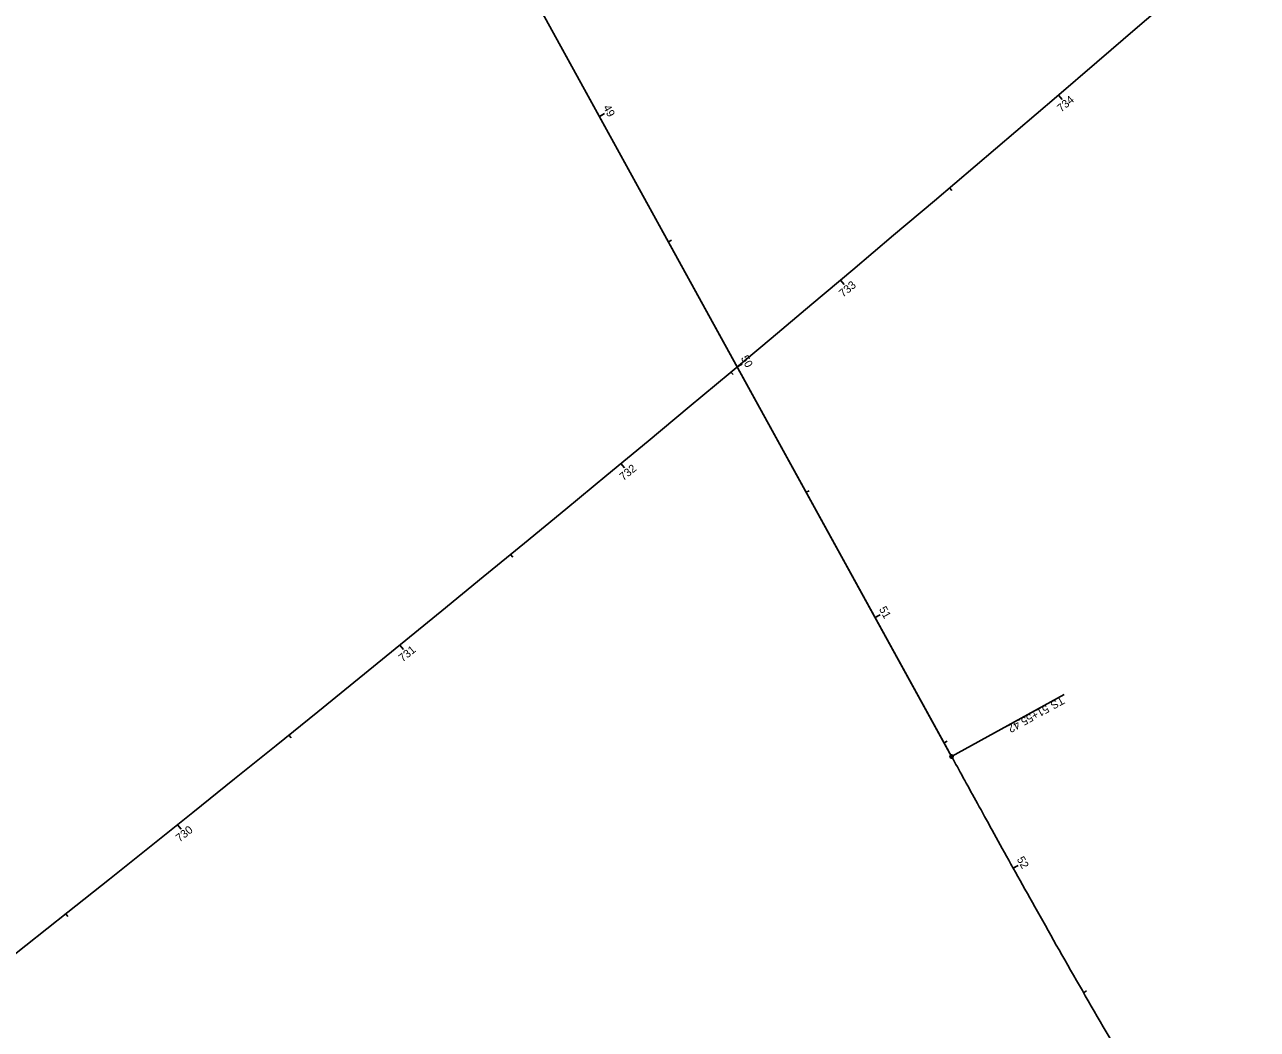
# Model space of a CAD drawing. Extents: x 1492452 to 1496782, y 514026 to 517659.
# Drawn here: x 1494046.8 to 1494477.9, y 515125.3 to 515476.4 of the extents above; entities that cross this region are included whole.
import ezdxf

# ---------------------------------------------------------------- set-up
doc = ezdxf.new("R2010")
doc.units = 0
for name, color, linetype in [('Default', 7, 'Continuous'), ('DT_X_Contour_Minor', 7, 'Continuous'), ('DT_X_TIN_Hull', 7, 'Continuous'), ('GE_X_Cells', 7, 'Continuous'), ('PV_X_EOP', 7, 'Continuous'), ('PV_X_Shoulder_Aggregate', 7, 'Continuous'), ('RD_X_GR_Rt', 7, 'Continuous'), ('RD_X_Wall', 7, 'Continuous'), ('SV_X_Top_of_Bank', 7, 'Continuous'), ('UT_X_Water_Cells', 7, 'Continuous'), ('VG_X_Cells', 7, 'Continuous'), ('XS_X_Ground_Line', 7, 'Continuous')]:
    doc.layers.add(name, color=color, linetype=linetype)

msp = doc.modelspace()

# ---------------------------------------------------------------- linework, layer by layer
at = {"layer": 'Default'}
msp.add_arc((1486425.91, 524780.42), 12277.67, 302.444021, 313.600151, dxfattribs=at)
at = {"layer": 'DT_X_Contour_Minor'}
msp.add_line((1494295.99, 515356.78), (1494297.74, 515357.74), dxfattribs=at)
at = {"layer": 'DT_X_TIN_Hull'}
for p, q in [((1494408.32, 515451.84), (1494409.62, 515450.32)), ((1494370.26, 515419.41), (1494371.04, 515418.5)), ((1494332.08, 515387.14), (1494333.36, 515385.61)), ((1494293.76, 515355.02), (1494294.53, 515354.1)), ((1494255.31, 515323.06), (1494256.58, 515321.52)), ((1494216.73, 515291.25), (1494217.49, 515290.32)), ((1494178.02, 515259.6), (1494179.28, 515258.05)), ((1494139.18, 515228.11), (1494139.94, 515227.18)), ((1494100.22, 515196.78), (1494101.47, 515195.22)), ((1494061.12, 515165.6), (1494061.87, 515164.66))]:
    msp.add_line(p, q, dxfattribs=at)
at = {"layer": 'GE_X_Cells'}
msp.add_arc((1486425.91, 524780.42), 12277.67, 302.444021, 313.600151, dxfattribs=at)
at = {"layer": 'PV_X_EOP'}
msp.add_line((1494370.94, 515220.63), (1494410.36, 515242.33), dxfattribs=at)
msp.add_circle((1494370.94, 515220.63), 0.6, dxfattribs=at)
at = {"layer": 'PV_X_Shoulder_Aggregate'}
for p, q in [((1494247.77, 515444.38), (1494249.52, 515445.35)), ((1494271.88, 515400.58), (1494272.93, 515401.16)), ((1494295.99, 515356.78), (1494297.74, 515357.74)), ((1494320.1, 515312.98), (1494321.15, 515313.55)), ((1494344.21, 515269.17), (1494345.97, 515270.14)), ((1494368.33, 515225.37), (1494369.38, 515225.95)), ((1494392.49, 515181.6), (1494394.24, 515182.57)), ((1494417.09, 515138.07), (1494418.13, 515138.67))]:
    msp.add_line(p, q, dxfattribs=at)
at = {"layer": 'RD_X_GR_Rt'}
msp.add_line((1494370.94, 515220.63), (1494410.36, 515242.33), dxfattribs=at)
msp.add_circle((1494370.94, 515220.63), 0.6, dxfattribs=at)
at = {"layer": 'RD_X_Wall'}
for p, q in [((1494247.77, 515444.38), (1494248.82, 515444.96)), ((1494295.99, 515356.78), (1494297.74, 515357.74)), ((1494344.21, 515269.17), (1494345.26, 515269.75)), ((1494392.49, 515181.6), (1494393.54, 515182.18))]:
    msp.add_line(p, q, dxfattribs=at)
at = {"layer": 'SV_X_Top_of_Bank'}
for q in [(1494370, 515222.33), (1494370.94, 515220.63)]:
    msp.add_line((1494054.87, 515794.8), q, dxfattribs=at)
msp.add_open_spline([(1494370.94, 515220.63), (1494373.62, 515215.76), (1494378.97, 515206.03), (1494389.71, 515186.57), (1494403.23, 515162.3), (1494419.72, 515133.34), (1494436.64, 515104.61), (1494451.2, 515080.96), (1494463.19, 515062.25), (1494469.31, 515052.97), (1494472.4, 515048.36)], degree=3, dxfattribs=at)
msp.add_open_spline([(1494370.94, 515220.63), (1494373.62, 515215.76), (1494378.97, 515206.03), (1494389.71, 515186.57), (1494403.23, 515162.3), (1494419.72, 515133.34), (1494436.64, 515104.61), (1494451.2, 515080.96), (1494463.19, 515062.25), (1494469.31, 515052.97), (1494472.4, 515048.36)], degree=3, dxfattribs=at)
at = {"layer": 'UT_X_Water_Cells'}
for p, q in [((1494408.32, 515451.84), (1494409.1, 515450.93)), ((1494332.08, 515387.14), (1494332.85, 515386.22)), ((1494255.31, 515323.06), (1494256.07, 515322.13)), ((1494178.02, 515259.6), (1494178.78, 515258.67)), ((1494100.22, 515196.78), (1494101.47, 515195.22))]:
    msp.add_line(p, q, dxfattribs=at)
at = {"layer": 'VG_X_Cells'}
msp.add_line((1494100.22, 515196.78), (1494101.47, 515195.22), dxfattribs=at)
at = {"layer": 'XS_X_Ground_Line'}
msp.add_line((1494370.94, 515220.63), (1494410.36, 515242.33), dxfattribs=at)
msp.add_circle((1494370.94, 515220.63), 0.6, dxfattribs=at)

# ---------------------------------------------------------------- texts
at = {"layer": 'DT_X_Contour_Minor'}
msp.add_text('50', height=2.8, rotation=298.8312, dxfattribs=at).set_placement((1494297.16, 515359.93))
at = {"layer": 'DT_X_TIN_Hull'}
for s, rotation, p in [('734', 40.5534, (1494409.3, 515445.71)), ('733', 40.0868, (1494332.99, 515380.98)), ('732', 39.6201, (1494256.16, 515316.89)), ('731', 39.1534, (1494178.95, 515253.53)), ('730', 38.6868, (1494100.97, 515190.59))]:
    msp.add_text(s, height=2.8, rotation=rotation, dxfattribs=at).set_placement(p)
at = {"layer": 'PV_X_EOP'}
for s, p in [('TS', (1494409.4, 515241.74)), ('51+55.42', (1494404.06, 515238.81))]:
    msp.add_text(s, height=2.8, rotation=208.8312, dxfattribs=at).set_placement(p)
at = {"layer": 'PV_X_Shoulder_Aggregate'}
for s, rotation, p in [('49', 298.8312, (1494248.95, 515447.51)), ('50', 298.8312, (1494297.16, 515359.93)), ('51', 298.8312, (1494345.47, 515272.18)), ('52', 299.0797, (1494393.66, 515184.75))]:
    msp.add_text(s, height=2.8, rotation=rotation, dxfattribs=at).set_placement(p)
at = {"layer": 'RD_X_GR_Rt'}
for s, p in [('TS', (1494409.4, 515241.74)), ('51+55.42', (1494404.06, 515238.81))]:
    msp.add_text(s, height=2.8, rotation=208.8312, dxfattribs=at).set_placement(p)
at = {"layer": 'RD_X_Wall'}
msp.add_text('50', height=2.8, rotation=298.8312, dxfattribs=at).set_placement((1494297.16, 515359.93))
at = {"layer": 'UT_X_Water_Cells'}
msp.add_text('730', height=2.8, rotation=38.6868, dxfattribs=at).set_placement((1494100.97, 515190.59))
at = {"layer": 'VG_X_Cells'}
msp.add_text('730', height=2.8, rotation=38.6868, dxfattribs=at).set_placement((1494100.97, 515190.59))
at = {"layer": 'XS_X_Ground_Line'}
for s, p in [('TS', (1494409.4, 515241.74)), ('51+55.42', (1494404.06, 515238.81))]:
    msp.add_text(s, height=2.8, rotation=208.8312, dxfattribs=at).set_placement(p)

doc.saveas('drawing.dxf')
